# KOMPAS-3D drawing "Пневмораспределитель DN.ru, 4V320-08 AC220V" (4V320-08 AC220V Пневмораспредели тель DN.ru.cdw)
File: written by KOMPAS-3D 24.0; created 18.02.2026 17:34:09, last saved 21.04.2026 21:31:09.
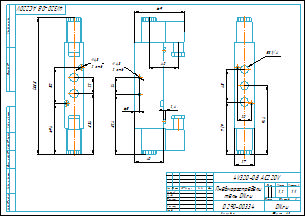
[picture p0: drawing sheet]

Document properties: Автор: R2D2; Форматы листов документа: A3; Полное имя файла: 4V320-08 AC220V Пневмораспределитель DN.RU.m3d; Масса: 1.2; Наименование: Пневмораспределитель DN.ru; Количество листов документа: 1; Примечание: D290-00334

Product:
- Part/product: Пневмораспределитель DN.ru  | designation 4V320-08 AC220V
    Масса: 1.2
    Раздел спецификации: Прочие изделия
    Форматы листов документа: A3
    Примечание: D290-00334

Views: Вид 1, Спереди, Проекционный вид 2, Проекционный вид 3
Referenced files in E:\Работа\Зайцев\Аксессуары для пневмоприводов\Пневмораспределители DN.ru\4V320 AC220V Пневмораспределитель DN.RU\4V320-08 AC220V Пневмораспределитель DN.RU\: 4V320-08 AC220V Пневмораспределитель DN.RU.m3d
Referenced files in E:\Работа\Зайцев\Для компаса\: чертеж DN.ru А3.cdt
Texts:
  чертеж DN.ru А3.cdt
  Пневмораспредели
  тель DN.ru
  Пневмораспределитель DN.ru
  4V320-08 AC220V Пневмораспределитель DN.ru
Dimensions and other numbers on the sheet: 0; 3; 2; 4; 94,4; 71,9; 45; 27; 5G1/4'; 20; 1; 4V320-08 AC220V; 4,3; 2 отв.; 69; 40; 82,4; 24; 6,5; 2,4; 188,8; 69,4; 50; 83,4; 22; 1:1; 1,2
